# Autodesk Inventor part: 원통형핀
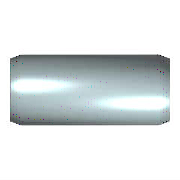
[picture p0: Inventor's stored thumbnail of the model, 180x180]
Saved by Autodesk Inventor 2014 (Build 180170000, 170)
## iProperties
IsCustomPart: 1
Created: 2012-02
Part Number: 원통형핀
Material: 강철, 연강
Description: 평행 핀
Document SubType Name: Modeling
Standard: KS B 1320
Designer: mduedu
Standards Organization: KS
Language: ko-KR
Size Designation: B 2 x  14
Categories: <MemberInstance><Categories><Category DisplayName="조임쇠" InternalName="e4da775c-781d-43d5-af7c-5136215cf5a6" Mnemonic="FSTN"><Category DisplayName="핀" InternalNa
Density: 1 g/cm^3
Appearance: 파란색 - 벽 페인트 - 광택
Author: mduedu
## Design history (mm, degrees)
sketch "스케치"
  geometry: C1 r 1 at (0, 0); 1 further point
  constraints: 1 centre point, 1 coincident
  dimensions: "d1" = 2 diameter of C1 (= NND)
extrude "본체" new body sketch "스케치" distance "d2" = 14 (= NLG); taper "d3" = 0 deg
chamfer "스케치2" distance "d8" = 0.35 (= PHH); stored, may be unused: angle "d9" = 15 deg (= FAWI), second distance "d12" = 0.35 (= PHH)
node "작업 평면1"
body "Solid1"
chamfer "모따기1" distance "d4" = 0.35 (= PHH); stored, may be unused: angle "d5" = 15 deg (= FAWI), second distance "d11" = 0.35 (= PHH)
other parameters: "NND" = 2 [user parameter; used in 1 equation term], "NLG" = 14 [user parameter; used in 1 equation term], "PHH" = 0.35 [user parameter; used in 4 equation terms], "FAWI" = 15 deg [user parameter; used in 2 equation terms], "d13" = 0, "d15" = 0, "d16" = 0, "KAH" = 0.25 [user parameter]
